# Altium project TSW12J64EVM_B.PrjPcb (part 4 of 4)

## Sheet TSW12J64EVM_B_10_InterfaceControl.SchDoc
size 431 x 279 mm; Date: Not shown in title block; ApprovedBy: Not shown in title block; CheckedBy: Not shown in title block; Author: Not shown in title block; CompanyName: Not shown in title block; Engineer: Not shown in title block; Organization: Not shown in title block; Address1: Not shown in title block; Address2: Not shown in title block; Address3: Not shown in title block; Address4: Not shown in title block; DocumentNumber: 10; Revision: Use project parameter SCH_Rev; SheetNumber: 10; SheetTotal: 11; PageSetup: Record=PageOptions¦CenterHorizontal=True¦CenterVertical=True¦PrintScale=1.00¦XCorrection=1.00¦YCorrection=1.00¦PrintKind=0¦BorderSize=5000000¦LeftOffset=0¦BottomOffset=0¦Orientation=2¦PaperLength=1000¦PaperWidth=1000¦Scale=100¦PaperSource=15¦PrintQuality=600¦MediaType=1¦DitherType=10¦PaperKind=Letter¦PrintScaleMode=1
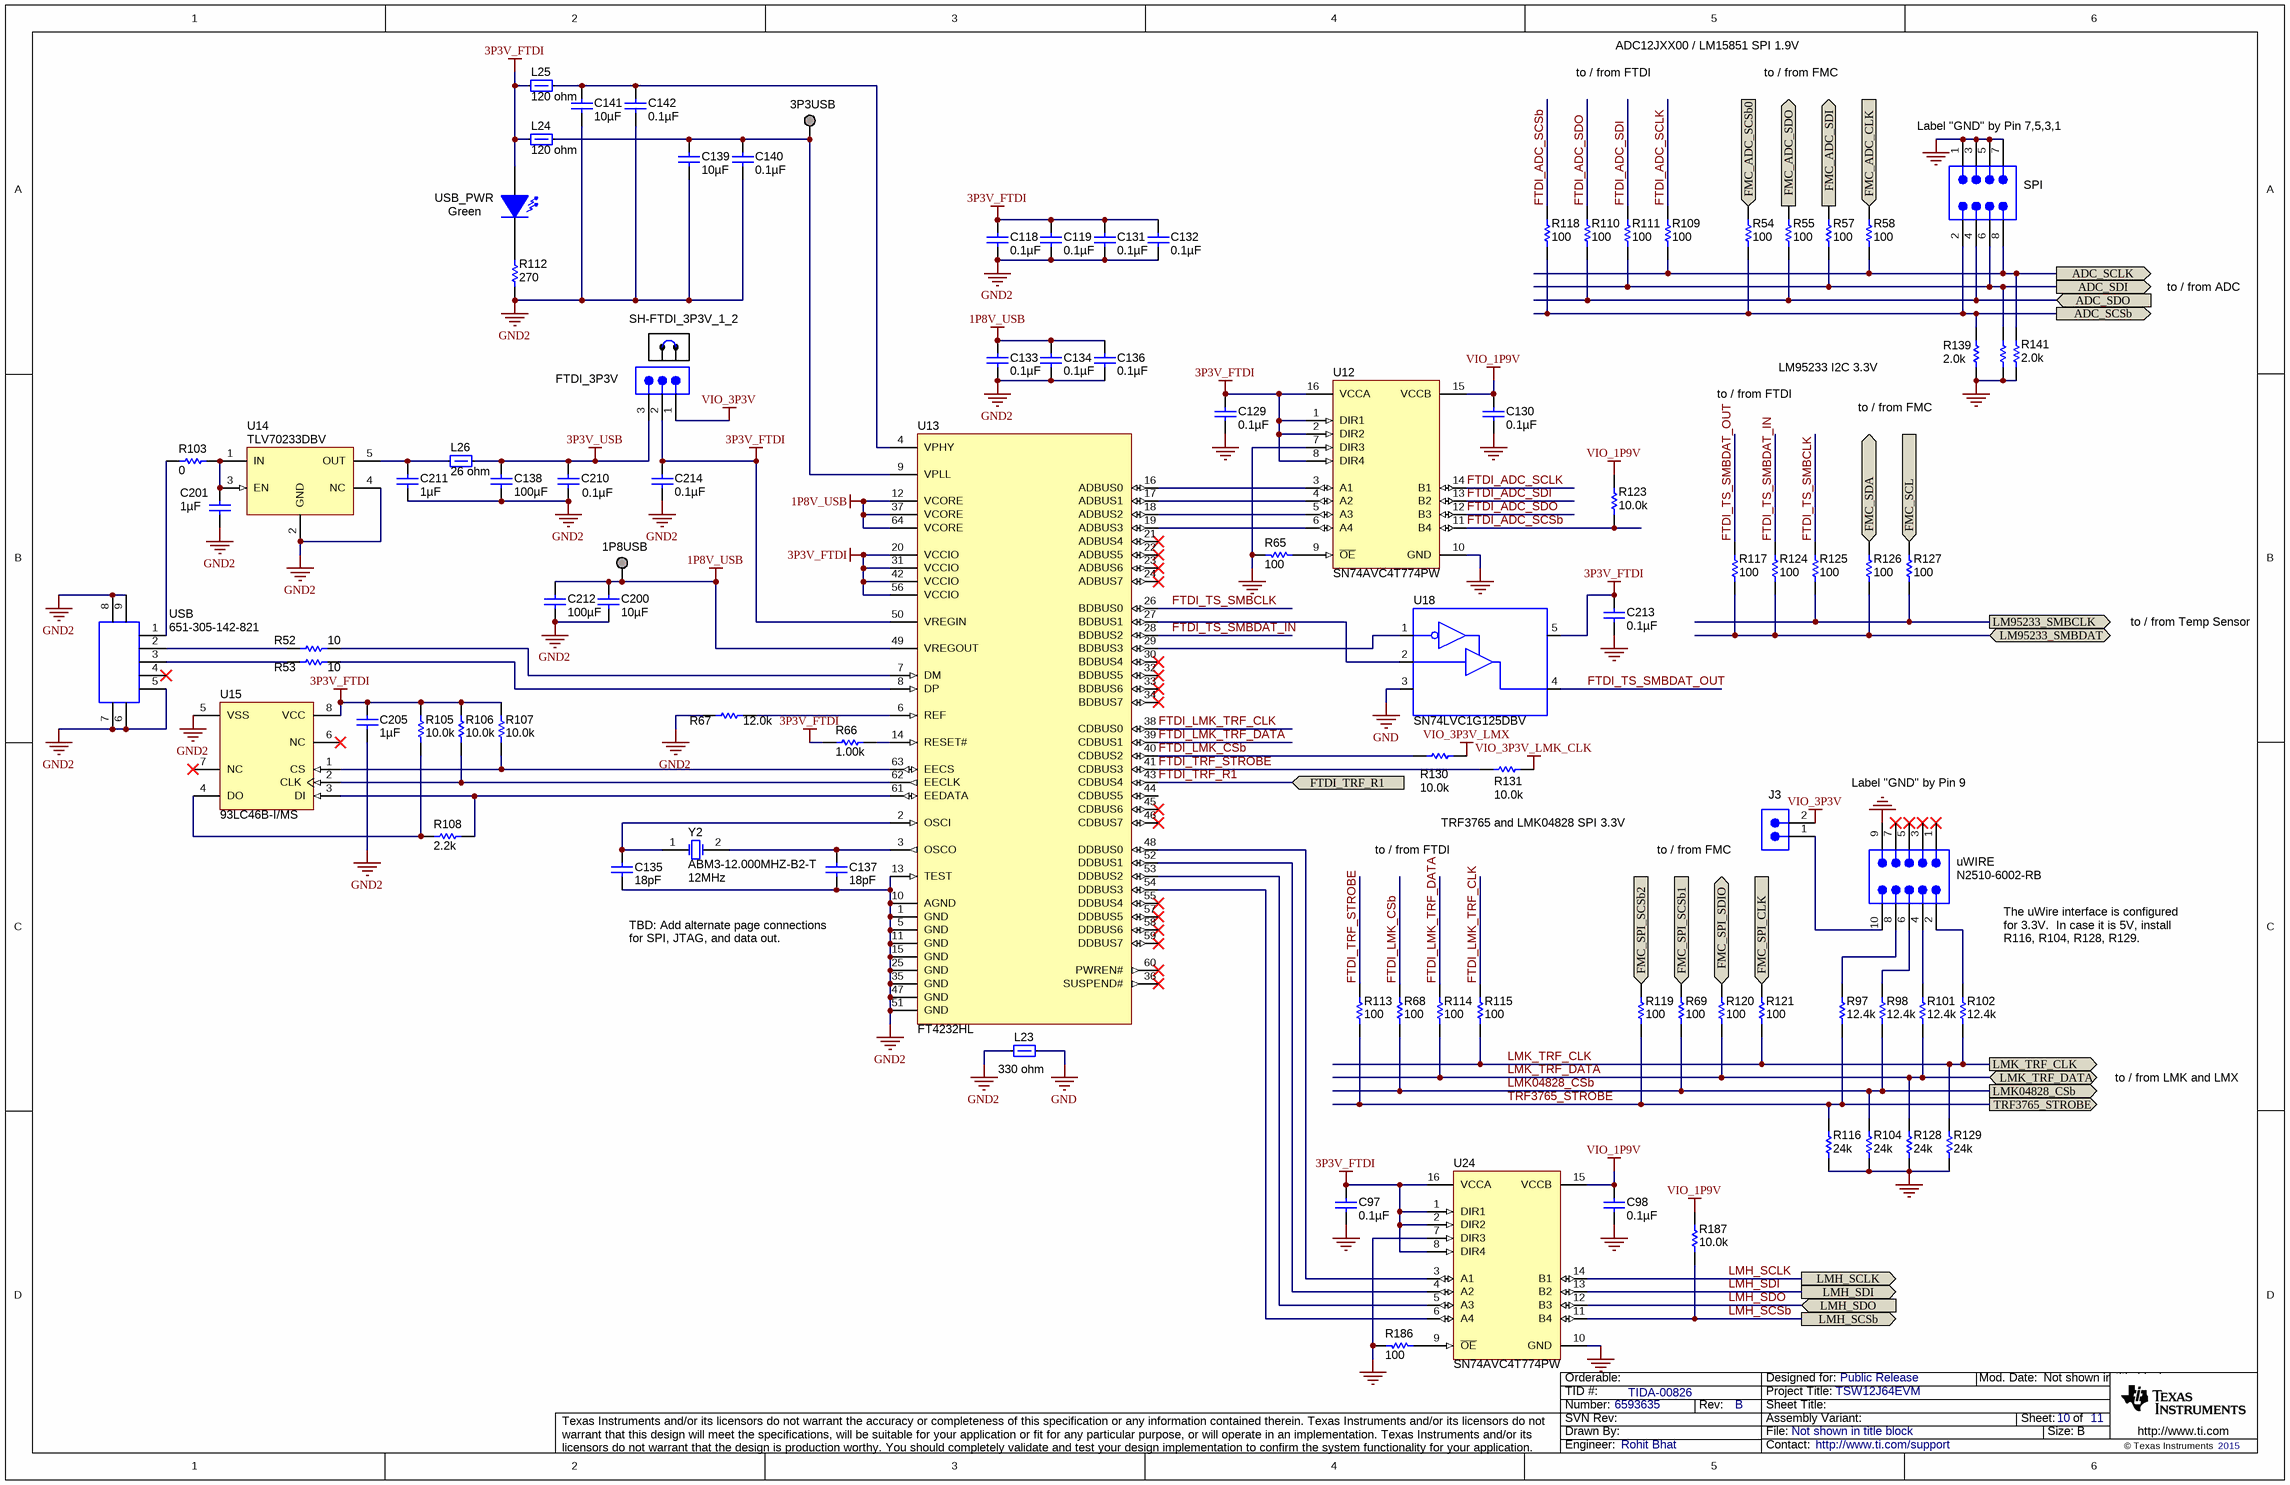
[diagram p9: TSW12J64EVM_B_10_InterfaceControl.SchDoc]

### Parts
1P8USB  TESTPOINT  [TESTPOINT]  (value not drawn)  (no BOM)
3P3USB  TESTPOINT  [TESTPOINT]  (value not drawn)  (no BOM)
C97  ValueDisplayed: 0.1µF  [0603L]  (hidden comment: 06033C104JAT2A)
C98  ValueDisplayed: 0.1µF  [0603L]  (hidden comment: 06033C104JAT2A)
C118  ValueDisplayed: 0.1µF  [0201]  (hidden comment: C0603X5R0J104K)
C119  ValueDisplayed: 0.1µF  [0201]  (hidden comment: C0603X5R0J104K)
C129  ValueDisplayed: 0.1µF  [0603L]  (hidden comment: 06033C104JAT2A)
C130  ValueDisplayed: 0.1µF  [0603L]  (hidden comment: 06033C104JAT2A)
C131  ValueDisplayed: 0.1µF  [0201]  (hidden comment: C0603X5R0J104K)
C132  ValueDisplayed: 0.1µF  [0201]  (hidden comment: C0603X5R0J104K)
C133  ValueDisplayed: 0.1µF  [0201]  (hidden comment: C0603X5R0J104K)
C134  ValueDisplayed: 0.1µF  [0201]  (hidden comment: C0603X5R0J104K)
C135  ValueDisplayed: 18pF  [0402L]  (hidden comment: GRM1555C1H180JA01D)
C136  ValueDisplayed: 0.1µF  [0201]  (hidden comment: C0603X5R0J104K)
C137  ValueDisplayed: 18pF  [0402L]  (hidden comment: GRM1555C1H180JA01D)
C138  ValueDisplayed: 100µF  [1206L]  (hidden comment: GRM31CR60J107ME39L)
C139  ValueDisplayed: 10µF  [0603L]  (hidden comment: C1608X5R1A106M)
C140  ValueDisplayed: 0.1µF  [0201]  (hidden comment: C0603X5R0J104K)
C141  ValueDisplayed: 10µF  [0603L]  (hidden comment: C1608X5R1A106M)
C142  ValueDisplayed: 0.1µF  [0201]  (hidden comment: C0603X5R0J104K)
C200  ValueDisplayed: 10µF  [0603L]  (hidden comment: C1608X5R1A106M)
C201  ValueDisplayed: 1µF  [0603L]  (hidden comment: C1608X5R1C105K)
C205  ValueDisplayed: 1µF  [0603L]  (hidden comment: C1608X5R1A105K)
C210  ValueDisplayed: 0.1µF  [0603L]  (hidden comment: 0603YC104JAT2A)
C211  ValueDisplayed: 1µF  [0603L]  (hidden comment: C1608X5R1C105K)
C212  ValueDisplayed: 100µF  [1206]  (hidden comment: GRM31CR60J107ME39L)
C213  ValueDisplayed: 0.1µF  [0603L]  (hidden comment: 06033C104JAT2A)
C214  ValueDisplayed: 0.1µF  [0201]  (hidden comment: C0603X5R0J104K)
FTDI_3P3V  TSW-103-07-G-S  [TSW-103-07-G-S]  (value not drawn)
J3  TSW-102-07-G-S  [TSW-102-07-G-S]  (value not drawn)
L23  value 330 ohm  [0603]  (hidden comment: BLM18SG331TN1D)
L24  value 120 ohm  [0603]  (hidden comment: BLM18SG121TN1D)
L25  value 120 ohm  [0603L]  (hidden comment: BLM18SG121TN1D)
L26  value 26 ohm  [0603]  (hidden comment: BLM18SG260TN1D)
R52  value 10  [0603L]  (hidden comment: CRCW060310R0JNEA)
R53  value 10  [0603L]  (hidden comment: CRCW060310R0JNEA)
R54  value 100  [0603L]  (hidden comment: CRCW0603100RJNEA)
R55  value 100  [0603L]  (hidden comment: CRCW0603100RJNEA)
R57  value 100  [0603L]  (hidden comment: CRCW0603100RJNEA)
R58  value 100  [0603L]  (hidden comment: CRCW0603100RJNEA)
R65  value 100  [0603L]  (hidden comment: CRCW0603100RJNEA)
R66  value 1.00k  [0603L]  (hidden comment: CRCW06031K00FKEA)
R67  value 12.0k  [0603L]  (hidden comment: RC0603FR-0712KL)
R68  value 100  [0603L]  (hidden comment: CRCW0603100RJNEA)
R69  value 100  [0603L]  (hidden comment: CRCW0603100RJNEA)
R97  value 12.4k  [0603L]  (hidden comment: CRCW060312K4FKEA)
R98  value 12.4k  [0603L]  (hidden comment: CRCW060312K4FKEA)
R101  value 12.4k  [0603L]  (hidden comment: CRCW060312K4FKEA)
R102  value 12.4k  [0603L]  (hidden comment: CRCW060312K4FKEA)
R103  value 0  [0603L]  (hidden comment: CRCW06030000Z0EA)
R104  value 24k  [0402L]  (hidden comment: CRCW040224K0JNED)
R105  value 10.0k  [0603L]  (hidden comment: CRCW060310K0FKEA)
R106  value 10.0k  [0603L]  (hidden comment: CRCW060310K0FKEA)
R107  value 10.0k  [0603L]  (hidden comment: CRCW060310K0FKEA)
R108  value 2.2k  [0603L]  (hidden comment: RC0603JR-072K2L)
R109  value 100  [0603L]  (hidden comment: CRCW0603100RJNEA)
R110  value 100  [0603L]  (hidden comment: CRCW0603100RJNEA)
R111  value 100  [0603L]  (hidden comment: CRCW0603100RJNEA)
R112  value 270  [0603L]  (hidden comment: CRCW0603270RJNEA)
R113  value 100  [0603L]  (hidden comment: CRCW0603100RJNEA)
R114  value 100  [0603L]  (hidden comment: CRCW0603100RJNEA)
R115  value 100  [0603L]  (hidden comment: CRCW0603100RJNEA)
R116  value 24k  [0402L]  (hidden comment: CRCW040224K0JNED)
R117  value 100  [0603L]  (hidden comment: CRCW0603100RJNEA)
R118  value 100  [0603L]  (hidden comment: CRCW0603100RJNEA)
R119  value 100  [0603L]  (hidden comment: CRCW0603100RJNEA)
R120  value 100  [0603L]  (hidden comment: CRCW0603100RJNEA)
R121  value 100  [0603L]  (hidden comment: CRCW0603100RJNEA)
R123  value 10.0k  [0603L]  (hidden comment: CRCW060310K0FKEA)
R124  value 100  [0603L]  (hidden comment: CRCW0603100RJNEA)
R125  value 100  [0603L]  (hidden comment: CRCW0603100RJNEA)
R126  value 100  [0603L]  (hidden comment: CRCW0603100RJNEA)
R127  value 100  [0603L]  (hidden comment: CRCW0603100RJNEA)
R128  value 24k  [0402L]  (hidden comment: CRCW040224K0JNED)
R129  value 24k  [0402L]  (hidden comment: CRCW040224K0JNED)
R130  value 10.0k  [0603L]  (hidden comment: CRCW060310K0FKEA)
R131  value 10.0k  [0603L]  (hidden comment: CRCW060310K0FKEA)
R139  value 2.0k  [0603L]  (hidden comment: CRCW06032K00JNEA)
R140  CRCW06032K00JNEA  [0603L]  (value not drawn)
R141  value 2.0k  [0603L]  (hidden comment: CRCW06032K00JNEA)
R186  value 100  [0603L]  (hidden comment: CRCW0603100RJNEA)
R187  value 10.0k  [0603L]  (hidden comment: CRCW060310K0FKEA)
SH-FTDI_3P3V_1_2  SNT-100-BK-G  [SNT-100-BK-G]  (value not drawn)
SPI  TSW-104-07-G-D  [TSW-104-07-G-D]  (value not drawn)
U12  SN74AVC4T774PW  [PW0016A_L]
U13  FT4232HL  [LQFP64_N]
U14  TLV70233DBV  [DBV0005A_N]
U15  93LC46B-I/MS  [MSOP-MS8_N]
U18  SN74LVC1G125DBV  [SOP-5_.95MM_(DBV)]
U24  SN74AVC4T774PW  [PW0016A_L]
USB  651-305-142-821  [CONN_USB-MINI-AB-651-305-142-821]
USB_PWR  value Green  [LED_LTST-C190]  (hidden comment: LTST-C190GKT)
uWIRE  N2510-6002-RB  [CONN_2510-6002]
Y2  ABM3-12.000MHZ-B2-T  Frequency: 12MHz  [XTAL_ABM3]

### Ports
ADC_SCLK (out), ADC_SCSb (out), ADC_SDI (out), ADC_SDO (in), FMC_ADC_CLK (in), FMC_ADC_SCSb0 (in), FMC_ADC_SDI (out), FMC_ADC_SDO (in), FMC_SCL (out), FMC_SDA (bidir), FMC_SPI_CLK (in), FMC_SPI_SCSb1 (in), FMC_SPI_SCSb2 (in), FMC_SPI_SDIO (bidir), FTDI_TRF_R1, LM95233_SMBCLK (out), LM95233_SMBDAT (bidir), LMH_SCLK (out), LMH_SCSb (out), LMH_SDI (out), LMH_SDO (in), LMK04828_CSb (out), LMK_TRF_CLK, LMK_TRF_DATA (bidir), TRF3765_STROBE (out)

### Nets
1P8V_USB: 1P8USB.1 C133.1 C134.1 C136.1 C200.1 C212.2 U13.12(VCORE) U13.37(VCORE) U13.49(VREGOUT) U13.64(VCORE)
3P3V_FTDI: C97.1 C118.1 C119.1 C129.1 C131.1 C132.1 C205.1 C213.1 C214.1 FTDI_3P3V.2 L24.1 L25.1 R66.2 R105.2 R106.2 R107.2 U12.1(DIR1) U12.2(DIR2) U12.8(DIR4) U12.16(VCCA) U13.20(VCCIO) U13.31(VCCIO) U13.42(VCCIO) U13.50(VREGIN) U13.56(VCCIO) U15.8(VCC) U18.5(VCC) U24.1(DIR1) U24.2(DIR2) U24.8(DIR4) U24.16(VCCA) USB_PWR.1(A)
3P3V_USB: C138.1 C210.1 FTDI_3P3V.3 L26.2
GND: C97.2 C98.2 C129.2 C130.2 C213.2 L23.2 R65.1 R104.1 R116.1 R128.1 R129.1 R139.1 R140.1 R141.1 R186.1 SPI.1 SPI.3 SPI.5 SPI.7 U12.7(DIR3) U12.10(GND) U18.3(GND) U24.7(DIR3) U24.10(GND) uWIRE.9
GND2: C118.2 C119.2 C131.2 C132.2 C133.2 C134.2 C135.2 C136.2 C137.2 C138.2 C139.2 C140.2 C141.2 C142.2 C200.2 C201.2 C205.2 C210.2 C211.2 C212.1 C214.2 L23.1 R67.1 R112.1 U13.1(GND) U13.5(GND) U13.10(AGND) U13.11(GND) U13.13(TEST) U13.15(GND) U13.25(GND) U13.35(GND) U13.47(GND) U13.51(GND) U14.2(GND) U14.4(NC) U15.5(VSS) USB.5 USB.6 USB.7 USB.8 USB.9
VIO_1P9V: C98.1 C130.1 R123.2 R187.2 U12.15(VCCB) U24.15(VCCB)
VIO_3P3V: FTDI_3P3V.1 J3.2
VIO_3P3V_LMK_CLK: R131.1
VIO_3P3V_LMX: R130.1
ADC_SCLK: R58.1 R109.1 R141.2 SPI.8 ; port ADC_SCLK
ADC_SCSb: R54.1 R118.1 R139.2 SPI.2 ; port ADC_SCSb
ADC_SDI: R57.1 R111.1 R140.2 SPI.6 ; port ADC_SDI
ADC_SDO: R55.1 R110.1 SPI.4 ; port ADC_SDO
FMC_ADC_CLK: R58.2 ; port FMC_ADC_CLK
FMC_ADC_SCSb0: R54.2 ; port FMC_ADC_SCSb0
FMC_ADC_SDI: R57.2 ; port FMC_ADC_SDI
FMC_ADC_SDO: R55.2 ; port FMC_ADC_SDO
FMC_SCL: R127.2 ; port FMC_SCL
FMC_SDA: R126.2 ; port FMC_SDA
FMC_SPI_CLK: R121.2 ; port FMC_SPI_CLK
FMC_SPI_SCSb1: R69.2 ; port FMC_SPI_SCSb1
FMC_SPI_SCSb2: R119.2 ; port FMC_SPI_SCSb2
FMC_SPI_SDIO: R120.2 ; port FMC_SPI_SDIO
FTDI_ADC_SCLK: R109.2 U12.14(B1)
FTDI_ADC_SCSb: R118.2 R123.1 U12.11(B4)
FTDI_ADC_SDI: R111.2 U12.13(B2)
FTDI_ADC_SDO: R110.2 U12.12(B3)
FTDI_LMK_CSb: R68.2 R130.2 U13.40(CDBUS2)
FTDI_LMK_TRF_CLK: R115.2 U13.38(CDBUS0)
FTDI_LMK_TRF_DATA: R114.2 U13.39(CDBUS1)
FTDI_TRF_R1: U13.43(CDBUS4) ; port FTDI_TRF_R1
FTDI_TRF_STROBE: R113.2 R131.2 U13.41(CDBUS3)
FTDI_TS_SMBCLK: R125.2 U13.26(BDBUS0)
FTDI_TS_SMBDAT_IN: R124.2 U13.28(BDBUS2)
FTDI_TS_SMBDAT_OUT: R117.2 U18.4(Y)
LM95233_SMBCLK: R125.1 R127.1 ; port LM95233_SMBCLK
LM95233_SMBDAT: R117.1 R124.1 R126.1 ; port LM95233_SMBDAT
LMH_SCLK: U24.14(B1) ; port LMH_SCLK
LMH_SCSb: R187.1 U24.11(B4) ; port LMH_SCSb
LMH_SDI: U24.13(B2) ; port LMH_SDI
LMH_SDO: U24.12(B3) ; port LMH_SDO
LMK04828_CSb: R68.1 R69.1 R98.1 R104.2 ; port LMK04828_CSb
LMK_TRF_CLK: R102.1 R115.1 R121.1 R129.2 ; port LMK_TRF_CLK
LMK_TRF_DATA: R101.1 R114.1 R120.1 R128.2 ; port LMK_TRF_DATA
TRF3765_STROBE: R97.1 R113.1 R116.2 R119.1 ; port TRF3765_STROBE
Net3P3USB_1: 3P3USB.1 C139.1 C140.1 L24.2 U13.9(VPLL)
NetC135_1: C135.1 U13.2(OSCI) Y2.1(OSC1)
NetC137_1: C137.1 U13.3(OSCO) Y2.2(OSC2)
NetC141_1: C141.1 C142.1 L25.2 U13.4(VPHY)
NetC201_1: C201.1 R103.2 U14.1(IN) U14.3(EN)
NetC211_1: C211.1 L26.1 U14.5(OUT)
NetJ3_1: J3.1 uWIRE.10
NetR52_1: R52.1 USB.2
NetR52_2: R52.2 U13.7(DM)
NetR53_1: R53.1 USB.3
NetR53_2: R53.2 U13.8(DP)
NetR65_2: R65.2 U12.9(~{OE})
NetR66_1: R66.1 U13.14(RESET#)
NetR67_2: R67.2 U13.6(REF)
NetR97_2: R97.2 uWIRE.8
NetR98_2: R98.2 uWIRE.6
NetR101_2: R101.2 uWIRE.4
NetR102_2: R102.2 uWIRE.2
NetR103_1: R103.1 USB.1
NetR105_1: R105.1 R108.2 U15.4(DO)
NetR106_1: R106.1 U13.62(EECLK) U15.2(CLK)
NetR107_1: R107.1 U13.63(EECS) U15.1(CS)
NetR108_1: R108.1 U13.61(EEDATA) U15.3(DI)
NetR112_2: R112.2 USB_PWR.2(K)
NetR186_2: R186.2 U24.9(~{OE})
NetU12_3: U12.3(A1) U13.16(ADBUS0)
NetU12_4: U12.4(A2) U13.17(ADBUS1)
NetU12_5: U12.5(A3) U13.18(ADBUS2)
NetU12_6: U12.6(A4) U13.19(ADBUS3)
NetU13_27: U13.27(BDBUS1) U18.2(A)
NetU13_29: U13.29(BDBUS3) U18.1(~OE)
NetU13_48: U13.48(DDBUS0) U24.3(A1)
NetU13_52: U13.52(DDBUS1) U24.4(A2)
NetU13_53: U13.53(DDBUS2) U24.5(A3)
NetU13_54: U13.54(DDBUS3) U24.6(A4)

Not connected (* = marked no-connect by the designer): U13 21(ADBUS4)* 22(ADBUS5)* 23(ADBUS6)* 24(ADBUS7)* 30(BDBUS4)* 32(BDBUS5)* 33(BDBUS6)* 34(BDBUS7)* 36(SUSPEND#)* 44(CDBUS5) 45(CDBUS6)* 46(CDBUS7)* 55(DDBUS4)* 57(DDBUS5)* 58(DDBUS6)* 59(DDBUS7)* 60(PWREN#)*; U15 6(NC)* 7(NC)*; USB 4*; uWIRE 1* 3* 5* 7*

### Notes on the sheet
- to / from FTDI
- ADC12JXX00 / LM15851 SPI 1.9V
- to / from FMC
- (near SPI) Label "GND" by Pin 7,5,3,1
- to / from ADC
- LM95233 I2C 3.3V
- to / from Temp Sensor
- TRF3765 and LMK04828 SPI 3.3V
- Label "GND" by Pin 9
- TBD: Add alternate page connections for SPI, JTAG, and data out.
- The uWire interface is configured for 3.3V.  In case it is 5V, install R116, R104, R128, R129.
- to / from LMK and LMX

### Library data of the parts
1P8USB 3P3USB = TESTPOINT: TEST POINT.  No entry in BOM.
C97 C98 C129 C130 C213 = 06033C104JAT2A: CAP, CERM, 0.1uF, 25V, +/-5%, X7R, 0603; Manufacturer: AVX; Polarized: N; CompType: Capacitor; U/M: EA; Cap_F: 0.0000001; Tolerance_%: 5; ESR_Ohm: 0.05; Value1: 0.05 ohm; VDC_V: 25; TaMin_C: -55; TaMax_C: 125; Cap_Case: 0603
C118 C119 C131-C134 C136 C140 C142 C214 = Capacitor: CAP, CERM, 0.1uF, 6.3V, X5R, 10%, 0201; Manufacturer: TDK; Polarized: N; U/M: EA
C135 C137 = GRM1555C1H180JA01D: CAP, CERM, 18pF, 50V, +/-5%, C0G/NP0, 0402; Manufacturer: MuRata; Polarized: N; CompType: Capacitor; U/M: EA; Cap_F: 0.000000000018; Tolerance_%: 5; Value1: Unknown; VDC_V: 50; TaMin_C: -55; TaMax_C: 125; Cap_Case: 0402
C138 = GRM31CR60J107ME39L: CAP, CERM, 100uF, 6.3V, +/-20%, X5R, 1206; Manufacturer: MuRata; Polarized: N; CompType: Capacitor; U/M: EA; Cap_F: 0.0001; Tolerance_%: 20; ESR_Ohm: 0.003; Value1: 0.003 ohm; VDC_V: 6.3; TaMin_C: -55; TaMax_C: 85; Cap_Case: 1206
C139 C141 C200 = C1608X5R1A106M: CAP, CERM, 10uF, 10V, +/-10%, C0G/NP0, 0603; Manufacturer: TDK; Polarized: N; CompType: Capacitor; U/M: EA; Cap_F: 0.00001; Tolerance_%: 10; ESR_Ohm: 0.0078; Value1: 0.0078 ohm; IRMS_A: 1.85; TaMin_C: -55; TaMax_C: 85; Cap_Case: 0603
C201 C211 = C1608X5R1C105K: CAP, CERM, 1uF, 16V, +/-10%, X5R, 0603; Manufacturer: TDK; Polarized: N; CompType: Capacitor; U/M: EA; Cap_F: 0.000001; Tolerance_%: 10; ESR_Ohm: 0.0057; Value1: 0.0057 ohm; VDC_V: 16; TaMin_C: -55; TaMax_C: 85; Cap_Case: 0603
C205 = C1608X5R1A105K: CAP, CERM, 1uF, 10V, +/-10%, X5R, 0603; Manufacturer: TDK; Polarized: N; CompType: Capacitor; U/M: EA; Cap_F: 0.000001; Tolerance_%: 10; ESR_Ohm: 0.0057; Value1: 0.0057 ohm; TaMin_C: -55; TaMax_C: 85; Cap_Case: 0603
C210 = 0603YC104JAT2A: CAP, CERM, 0.1uF, 16V, +/-5%, X7R, 0603; Manufacturer: AVX; Polarized: N; CompType: Capacitor; U/M: EA; Cap_F: 0.0000001; Tolerance_%: 5; ESR_Ohm: 0.039; Value1: 0.039 ohm; VDC_V: 16; TaMin_C: -55; TaMax_C: 125; Cap_Case: 0603
C212 = GRM31CR60J107ME39L: CAP, CERM, 100uF, 6.3V, +/-20%, X5R, 1206; Manufacturer: MuRata; Polarized: N; CompType: Capacitor; U/M: EA; Cap_F: 0.0001; Tolerance_%: 20; ESR_Ohm: 0.003; Value1: 0.003 ohm; VDC_V: 6.3; TaMin_C: -55; TaMax_C: 85
FTDI_3P3V = TSW-103-07-G-S: Header, TH, 100mil, 3x1, Gold plated, 230 mil above insulator; Manufacturer: Samtec, Inc.; Alternate Manufacturer: Any; Alternate PartNumber: Equivalent; U/M: EA
J3 = TSW-102-07-G-S: Header, TH, 100mil, 2x1, Gold plated, 230 mil above insulator; Manufacturer: Samtec, Inc.; U/M: EA
L23 = BLM18SG331TN1D: 1.5A Ferrite Bead, 330 ohm @ 100MHz, SMD; Manufacturer: MuRata; Imax_A: 1.5; DCR_ohm: 0.07; Value1: 0.07 ohm; ZTyp@100MHz_Ohm: 330; U/M: EA
L24 L25 = BLM18SG121TN1D: 3A Ferrite Bead, 120 ohm @ 100MHz, SMD; Manufacturer: MuRata; Imax_A: 3; DCR_ohm: 0.025; Value1: 0.025 ohm; ZTyp@100MHz_Ohm: 120; U/M: EA
L26 = BLM18SG260TN1D: 6A Ferrite Bead, 26 ohm @ 100MHz, SMD; Manufacturer: MuRata; Imax_A: 6; DCR_ohm: 0.007; Value1: 0.007 ohm; ZTyp@100MHz_Ohm: 26; U/M: EA
R52 R53 = CRCW060310R0JNEA: RES, 10 ohm, 5%, 0.1W, 0603; Manufacturer: Vishay-Dale; CompType: Resistor; Value_Code: 10R0; Tolerance_%: 5; Power_W: 0.1; VDC_V: 75; TempCo: 200 ppm/C; EIA_Code: E24; U/M: EA
R54 R55 R57 R58 R65 R68 R69 R109-R111 R113-R115 R117-R121 R124-R127 R186 = CRCW0603100RJNEA: RES, 100 ohm, 5%, 0.1W, 0603; Manufacturer: Vishay-Dale; CompType: Resistor; Value_Code: 100R; Tolerance_%: 5; Power_W: 0.1; VDC_V: 75; TempCo: 200 ppm/C; EIA_Code: E24; U/M: EA
R66 = CRCW06031K00FKEA: RES, 1.00k ohm, 1%, 0.1W, 0603; Manufacturer: Vishay-Dale; CompType: Resistor; Tolerance_%: 1; VDC_V: 75; Power_W: 0.1; Res_ohm: 1000; TempCo_ppm/C: 100; Value_Code: 1k00; EIA_Code: E96; U/M: EA
R67 = RC0603FR-0712KL: RES, 12.0k ohm, 1%, 0.1W, 0603; Manufacturer: Yageo America; CompType: Resistor; Res_ohm: 12000; Value_Code: 12k0; Tolerance_%: 1; Power_W: 0.1; VDC_V: 150; TempCo: 200 ppm/C; U/M: EA
R97 R98 R101 R102 = CRCW060312K4FKEA: RES, 12.4k ohm, 1%, 0.1W, 0603; Manufacturer: Vishay-Dale; CompType: Resistor; Res_ohm: 12400; Value_Code: 12k4; Tolerance_%: 1; Power_W: 0.1; VDC_V: 75; TempCo: 100 ppm/C; EIA_Code: E96; U/M: EA
R103 = CRCW06030000Z0EA: RES, 0 ohm, 5%, 0.1W, 0603; Manufacturer: Vishay-Dale; CompType: Resistor; Value_Code: 0000; Tolerance_%: 5; Power_W: 0.1; VDC_V: 75; TempCo: 200 ppm/C; EIA_Code: E24; U/M: EA
R104 R116 R128 R129 = CRCW040224K0JNED: RES, 24k ohm, 5%, 0.063W, 0402; Manufacturer: Vishay-Dale; CompType: Resistor; Res_ohm: 24000; Value_Code: 24k0; Tolerance_%: 5; Power_W: 0.063; VDC_V: 50; TempCo: 200 ppm/C; EIA_Code: E24; U/M: EA
R105-R107 R123 R130 R131 R187 = CRCW060310K0FKEA: RES, 10.0k ohm, 1%, 0.1W, 0603; Manufacturer: Vishay-Dale; CompType: Resistor; Res_ohm: 10000; Value_Code: 10k0; Tolerance_%: 1; Power_W: 0.1; VDC_V: 75; TempCo: 100 ppm/C; EIA_Code: E96; U/M: EA
R108 = RC0603JR-072K2L: RES, 2.2k ohm, 5%, 0.1W, 0603; Manufacturer: Yageo America; CompType: Resistor; Res_ohm: 2200; Value_Code: 2k20; Tolerance_%: 5; Power_W: 0.1; VDC_V: 50; TempCo: 100 ppm/C; EIA_Code: E24; U/M: EA
R112 = CRCW0603270RJNEA: RES, 270 ohm, 5%, 0.1W, 0603; Manufacturer: Vishay-Dale; Alternate Manufacturer: Any; Alternate PartNumber: Equivalent; CompType: Resistor; Value_Code: 270R; Tolerance_%: 5; Power_W: 0.1; VDC_V: 75; TempCo: 200 ppm/C; EIA_Code: E24; U/M: EA
R139-R141 = CRCW06032K00JNEA: RES, 2.0k ohm, 5%, 0.1W, 0603; Manufacturer: Vishay-Dale; CompType: Resistor; Res_ohm: 2000; Value_Code: 2k00; Tolerance_%: 5; Power_W: 0.1; VDC_V: 75; TempCo: 200 ppm/C; EIA_Code: E24; U/M: EA
SH-FTDI_3P3V_1_2 = SNT-100-BK-G: Shunt, 100mil, Gold plated, Black; Manufacturer: Samtec, Inc.; Alternate Manufacturer: 3M; Alternate PartNumber: 969102-0000-DA; Value: 1x2; Note: You can "mate" this to a header by matching the designator.  i.e. use SH-J3 for header J3
SPI = TSW-104-07-G-D: Header, TH, 100mil, 4x2, Gold plated, 230 mil above insulator; Manufacturer: Samtec, Inc.; U/M: EA
U12 U24 = SN74AVC4T774PW: 4-BIT DUAL-SUPPLY BUS TRANSCEIVER WITH CONFIGURABLE VOLTAGE TRANSLATION AND 3-STATE OUTPUTS, PW0016A; Alternate Manufacturer: None; Manufacturer: Texas Instruments; SymbolCreator: a0411947; CompType: IC; U/M: EA
U13 = FT4232HL: Quad High Speed USB to Multipurpose UART/MPSSE IC; Manufacturer: FTDI; SymbolCreator: a0411947
U14 = TLV70233DBV: 300-mA, Low-IQ, Low-Dropout Regulator, DBV0005A; Alternate Manufacturer: None; Manufacturer: Texas Instruments; SymbolCreator: a0411947; CompType: IC; U/M: EA
U15 = 93LC46B-I/MS: 1K, 64x16-bit, 2.5V Microwire Serial EEPROM, 8-Pin MSOP, Industrial Temperature; Manufacturer: Microchip Technology
U18 = SN74LVC1G125DBV: IC, Single Bus Buffer Gate With 3-States Output; Manufacturer: TI; Alternate Manufacturer: None; Area: 24,883
USB = 651-305-142-821: MINI USB 2.0 SMT TYPE AB 5 CONTACTS R/A, SMD; Manufacturer: Wurth Elektronik eiSos; SymbolCreator: a0799628; CompType: Connector; U/M: EA
USB_PWR = LTST-C190GKT: LED, Green, SMD; Manufacturer: Lite-On; Vf_V: 2.1; Value2: 2.1V; Io_A: 0.02; Power_TotalModule: 0.1; Value1: 0.1W; U/M: EA
uWIRE = N2510-6002-RB: Connector, 100mil Shrouded, 5x2, High-Temperature, Gold, TH; Manufacturer: 3M; SymbolCreator: a0412235; U/M: EA
Y2 = ABM3-12.000MHZ-B2-T: Crystal, 12Mhz, 18pF, SMD; Manufacturer: Abracon Corportation; SymbolCreator: a0412235; U/M: EA; TaMin_C: -20; TaMax_C: 70; Frequency Stability: ±50ppm

## Sheet TSW12J64EVM_B_11_Hardware.SchDoc
size 431 x 279 mm; Date: Not shown in title block; ApprovedBy: Not shown in title block; CheckedBy: Not shown in title block; Author: Not shown in title block; CompanyName: Not shown in title block; Engineer: Not shown in title block; Organization: Not shown in title block; Address1: Not shown in title block; Address2: Not shown in title block; Address3: Not shown in title block; Address4: Not shown in title block; DocumentNumber: 11; Revision: Use project parameter SCH_Rev; SheetNumber: 11; SheetTotal: 11; PageSetup: Record=PageOptions¦CenterHorizontal=True¦CenterVertical=True¦PrintScale=1.00¦XCorrection=1.00¦YCorrection=1.00¦PrintKind=0¦BorderSize=5000000¦LeftOffset=0¦BottomOffset=0¦Orientation=2¦PaperLength=1000¦PaperWidth=1000¦Scale=100¦PaperSource=15¦PrintQuality=600¦MediaType=1¦DitherType=10¦PaperKind=Letter¦PrintScaleMode=1
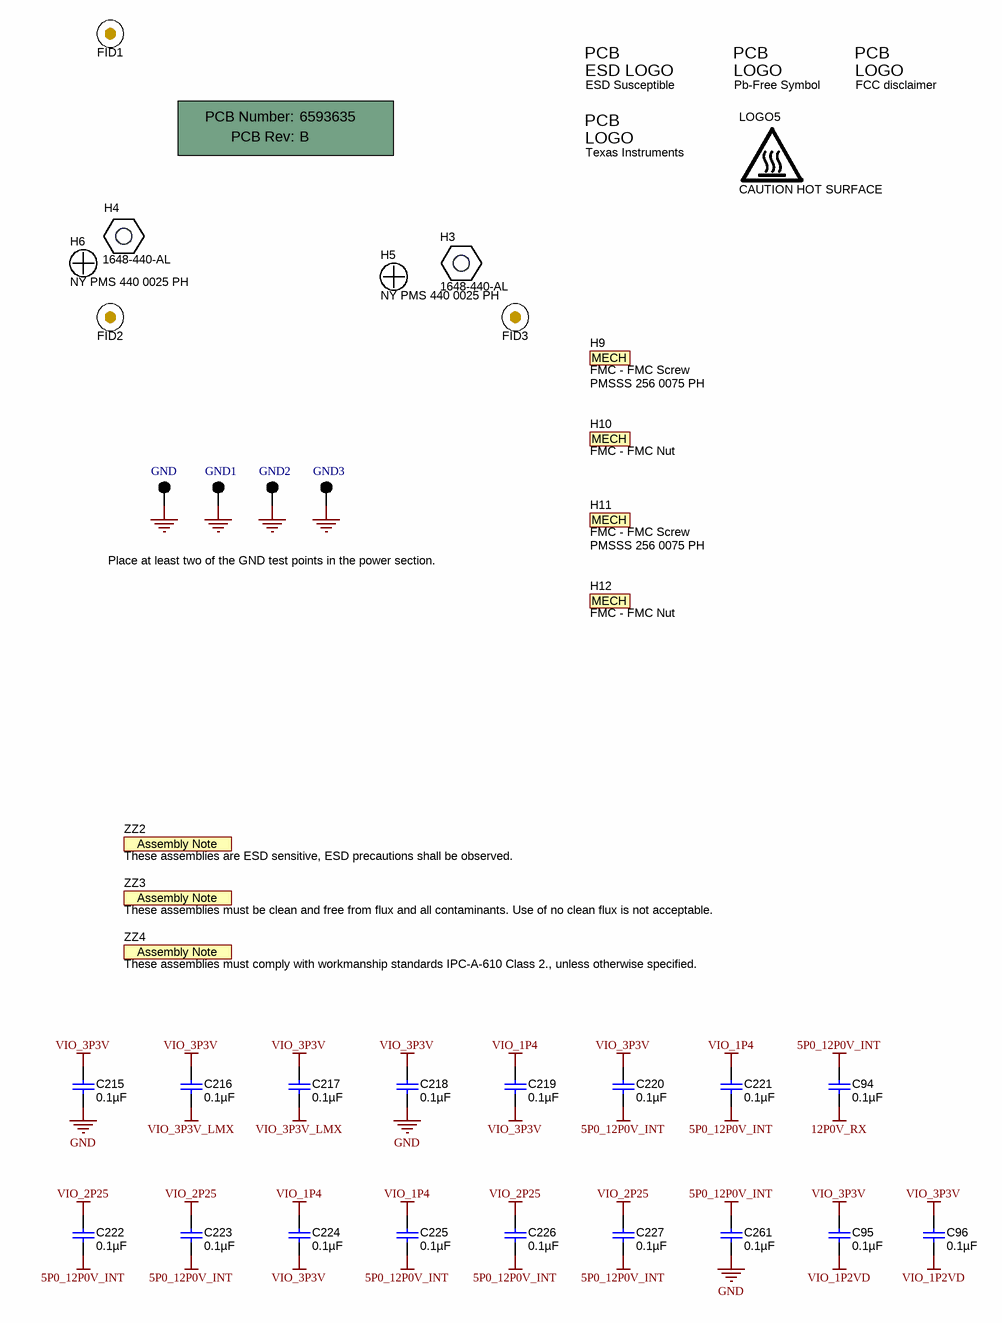
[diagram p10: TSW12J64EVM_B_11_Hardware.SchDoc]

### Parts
!PCB  Printed Circuit Board  (value not drawn)  (mechanical)
C94  ValueDisplayed: 0.1µF  [0402L]  (hidden comment: GRM155R71A104KA01D)
C95  ValueDisplayed: 0.1µF  [0402L]  (hidden comment: GRM155R71A104KA01D)
C96  ValueDisplayed: 0.1µF  [0402L]  (hidden comment: GRM155R71A104KA01D)
C215  ValueDisplayed: 0.1µF  [0402L]  (hidden comment: GRM155R71A104KA01D)
C216  ValueDisplayed: 0.1µF  [0402L]  (hidden comment: GRM155R71A104KA01D)
C217  ValueDisplayed: 0.1µF  [0402L]  (hidden comment: GRM155R71A104KA01D)
C218  ValueDisplayed: 0.1µF  [0402L]  (hidden comment: GRM155R71A104KA01D)
C219  ValueDisplayed: 0.1µF  [0402L]  (hidden comment: GRM155R71A104KA01D)
C220  ValueDisplayed: 0.1µF  [0402L]  (hidden comment: GRM155R71A104KA01D)
C221  ValueDisplayed: 0.1µF  [0402L]  (hidden comment: GRM155R71A104KA01D)
C222  ValueDisplayed: 0.1µF  [0402L]  (hidden comment: GRM155R71A104KA01D)
C223  ValueDisplayed: 0.1µF  [0402L]  (hidden comment: GRM155R71A104KA01D)
C224  ValueDisplayed: 0.1µF  [0402L]  (hidden comment: GRM155R71A104KA01D)
C225  ValueDisplayed: 0.1µF  [0402L]  (hidden comment: GRM155R71A104KA01D)
C226  ValueDisplayed: 0.1µF  [0402L]  (hidden comment: GRM155R71A104KA01D)
C227  ValueDisplayed: 0.1µF  [0402L]  (hidden comment: GRM155R71A104KA01D)
C261  ValueDisplayed: 0.1µF  [0402L]  (hidden comment: GRM155R71A104KA01D)
FID1  Fiducial  [Fiducial10-30]  (value not drawn)
FID2  Fiducial  [Fiducial10-30]  (value not drawn)
FID3  Fiducial  [Fiducial10-30]  (value not drawn)
GND  5011  [Keystone5011]  (value not drawn)
GND1  5011  [Keystone5011]  (value not drawn)
GND2  5011  [Keystone5011]  (value not drawn)
GND3  5011  [Keystone5011]  (value not drawn)
H3  1648-440-AL  [Keystone_1902C]
H4  1648-440-AL  [Keystone_1902C]
H5  NY PMS 440 0025 PH  [NY PMS 440 0025 PH]
H6  NY PMS 440 0025 PH  [NY PMS 440 0025 PH]
H9  FMC - FMC Screw  PartNumber: PMSSS 256 0075 PH  (mechanical)
H10  FMC - FMC Nut  (mechanical)
H11  FMC - FMC Screw  PartNumber: PMSSS 256 0075 PH  (mechanical)
H12  FMC - FMC Nut  (mechanical)
Logo1  ESD Susceptible  [ESD_Overlay_Small]  (no BOM)
Logo2  Texas Instruments  [TI_Symbol_Overlay_Small]  (no BOM)
Logo3  Pb-Free Symbol  [Pb-Free_Overlay_Small]  (no BOM)
Logo4  FCC disclaimer  [FCC_disclaimer]  (no BOM)
LOGO5  CAUTION HOT SURFACE  [IEC_HotSurface_Small]  (no BOM)
ZZ2  These assemblies are ESD sensitive, ESD precautions shall be observed.  [AssemblyNote]  (no BOM)
ZZ3  These assemblies must be clean and free from flux and all contaminants. Use of no clean flux is not acceptable.  [AssemblyNote]  (no BOM)
ZZ4  These assemblies must comply with workmanship standards IPC-A-610 Class 2., unless otherwise specified.  [AssemblyNote]  (no BOM)

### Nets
5P0_12P0V_INT: C94.1 C220.2 C221.2 C222.2 C223.2 C225.2 C226.2 C227.2 C261.1
12P0V_RX: C94.2
GND: C215.2 C218.2 C261.2 GND.1 GND1.1 GND2.1 GND3.1
VIO_1P2VD: C95.2 C96.2
VIO_1P4: C219.1 C221.1 C224.1 C225.1
VIO_2P25: C222.1 C223.1 C226.1 C227.1
VIO_3P3V: C95.1 C96.1 C215.1 C216.1 C217.1 C218.1 C219.2 C220.1 C224.2
VIO_3P3V_LMX: C216.2 C217.2

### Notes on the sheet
- Place at least two of the GND test points in the power section.

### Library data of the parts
!PCB = PCB: Manufacturer: Any; PartNumber: 6593635; SymbolCreator: a0412235
C94-C96 C215-C227 C261 = GRM155R71A104KA01D: CAP, CERM, 0.1uF, 10V, +/-10%, X7R, 0402; Manufacturer: MuRata; Polarized: N; CompType: Capacitor; U/M: EA; Cap_F: 0.0000001; Tolerance_%: 10; TaMin_C: -55; TaMax_C: 125; Cap_Case: 0402
FID1-FID3 = Fiducial: Fiducial mark.  There is nothing to buy or mount.; SymbolCreator: codlsc
GND GND1-GND3 = 5011: Test Point, TH, Multipurpose, Black; Manufacturer: Keystone Electronics; CompType: Test Point Loop
H3 H4 = 1902C: Standoff, Round, 3/16"  x 1-3/16"L #4-40 Aluminum; Manufacturer: RAF; CompType: Hardware; U/M: EA
H5 H6 = NY PMS 440 0025 PH: Machine Screw, Round, #4-40 x 1/4, Nylon, Philips panhead; Manufacturer: B&F Fastener Supply; CompType: Hardware; SymbolCreator: codlsc; U/M: EA
H9 H11 = MechPart: MACHINE SCREW PAN PHILLIPS 2-56; Manufacturer: B&F Fastner Supply; SymbolCreator: codlsc; CompType: Mechanical; U/M: EA
H10 H12 = MechPart: HEX NUT 3/16" STN STEEL 2-56; Manufacturer: B & F Fastener Supply; PartNumber: HNSS256; SymbolCreator: codlsc; CompType: Mechanical; U/M: EA
Logo1 = ESD_Susceptible: ESD Susceptible Symbol; SymbolCreator: codlsc
Logo2 = TI_Logo: Texas Instrument Corporate Signature; SymbolCreator: codlsc
Logo3 = Pb-Free: SymbolCreator: a0412235
Logo4 = FCC_disclaimer: SymbolCreator: codlsc
LOGO5 = IEC_HotSurface: IEC 61010-1 Hot Surface Warning; SymbolCreator: a0412235
ZZ2-ZZ4 = AssemblyNote: SymbolCreator: codlsc

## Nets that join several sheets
5P0_12P0V_INT: TSW12J64EVM_B_8_Power (16 pins), TSW12J64EVM_B_9_Power (C382.1 C383.1 U43.2), TSW12J64EVM_B_11_Hardware (9 pins)
12P0V_RX: TSW12J64EVM_B_5_FMC (FMC_RX1.C35 FMC_RX1.C37), TSW12J64EVM_B_8_Power (EXT5V_FMC12V.3), TSW12J64EVM_B_11_Hardware (C94.2)
GND: TSW12J64EVM_B_1_FRONT_END (26 pins), TSW12J64EVM_B_2_RELAY_CONTROL (75 pins), TSW12J64EVM_B_3_ANALOG_IN (30 pins), TSW12J64EVM_B_4_ADC_IO (87 pins), TSW12J64EVM_B_5_FMC (164 pins), TSW12J64EVM_B_6_TRF3765 (64 pins), TSW12J64EVM_B_8_Power (82 pins), TSW12J64EVM_B_9_Power (76 pins), TSW12J64EVM_B_10_InterfaceControl (25 pins), TSW12J64EVM_B_11_Hardware (7 pins)
VIO_1P2VA: TSW12J64EVM_B_4_ADC_IO (18 pins), TSW12J64EVM_B_8_Power (C177.1 C188.1 L15.2)
VIO_1P2VD: TSW12J64EVM_B_4_ADC_IO (28 pins), TSW12J64EVM_B_8_Power (C189.1 C197.1 L16.2), TSW12J64EVM_B_11_Hardware (C95.2 C96.2)
VIO_1P4: TSW12J64EVM_B_8_Power (5 pins), TSW12J64EVM_B_11_Hardware (C219.1 C221.1 C224.1 C225.1)
VIO_1P9V: TSW12J64EVM_B_4_ADC_IO (20 pins), TSW12J64EVM_B_8_Power (6 pins), TSW12J64EVM_B_9_Power (5 pins), TSW12J64EVM_B_10_InterfaceControl (6 pins)
VIO_2P25: TSW12J64EVM_B_8_Power (5 pins), TSW12J64EVM_B_11_Hardware (C222.1 C223.1 C226.1 C227.1)
VIO_3: TSW12J64EVM_B_1_FRONT_END (D3.2), TSW12J64EVM_B_9_Power (C410.1 C411.1 L54.2)
VIO_3P3V: TSW12J64EVM_B_4_ADC_IO (15 pins), TSW12J64EVM_B_8_Power (C153.1 C163.1 L9.2), TSW12J64EVM_B_10_InterfaceControl (FTDI_3P3V.1 J3.2), TSW12J64EVM_B_11_Hardware (9 pins)
VIO_3P3V_LMK_CLK: TSW12J64EVM_B_8_Power (C116.1 C171.1 L13.2), TSW12J64EVM_B_10_InterfaceControl (R131.1)
VIO_3P3V_LMX: TSW12J64EVM_B_6_TRF3765 (19 pins), TSW12J64EVM_B_8_Power (C144.1 C152.1 L6.2), TSW12J64EVM_B_10_InterfaceControl (R130.1), TSW12J64EVM_B_11_Hardware (C216.2 C217.2)
VIO_3P75_U19: TSW12J64EVM_B_3_ANALOG_IN (13 pins), TSW12J64EVM_B_9_Power (C280.1 C281.1 L43.2 VIO_3P75_U19.1)
VIO_3P75_U23: TSW12J64EVM_B_3_ANALOG_IN (12 pins), TSW12J64EVM_B_4_ADC_IO (R183.1), TSW12J64EVM_B_9_Power (C297.1 C298.1 L45.2 VIO_3P75_U23.1)
VIO_4P05V: TSW12J64EVM_B_8_Power (6 pins), TSW12J64EVM_B_9_Power (L35.1 L36.1 L40.1 L53.1)
VIO_5V_DRV: TSW12J64EVM_B_2_RELAY_CONTROL (14 pins), TSW12J64EVM_B_9_Power (C401.1 C402.1 FL2.3 VIO_5V_DRV.1)
VIO_5V_LMC: TSW12J64EVM_B_2_RELAY_CONTROL (62 pins), TSW12J64EVM_B_9_Power (C395.1 C396.1 FL1.3 VIO_5V_LMC.1)
VIO_5V_LMH: TSW12J64EVM_B_1_FRONT_END (C353.1 C413.1 OFFSET_ADJ.1 U40.5), TSW12J64EVM_B_9_Power (C391.1 C392.1 L51.2 VIO_5V_LMH.1)
VIO_5V_LOGIC: TSW12J64EVM_B_1_FRONT_END (10 pins), TSW12J64EVM_B_9_Power (C398.1 C399.1 FL3.3 VIO_5V_LOGIC.1)
VIO_-1P25_U19: TSW12J64EVM_B_3_ANALOG_IN (10 pins), TSW12J64EVM_B_9_Power (C289.1 C290.1 L44.2 VIO_-1P25_U19.1)
VIO_-1P25_U23: TSW12J64EVM_B_3_ANALOG_IN (9 pins), TSW12J64EVM_B_4_ADC_IO (R182.1), TSW12J64EVM_B_9_Power (C299.1 C300.1 L46.2 VIO_-1P25_U23.1)
VIO_-3: TSW12J64EVM_B_1_FRONT_END (D3.1), TSW12J64EVM_B_9_Power (C404.1 C405.1 L52.2)
VIO_-3_LMH: TSW12J64EVM_B_1_FRONT_END (C354.1 C414.2 OFFSET_ADJ.3 U40.2), TSW12J64EVM_B_9_Power (C358.1 C359.1 L48.2)
ADC_OR_T0: TSW12J64EVM_B_4_ADC_IO (D2.2 OR.3 U2.25), TSW12J64EVM_B_5_FMC (FMC_RX1.G27)
ADC_OR_T1: TSW12J64EVM_B_4_ADC_IO (D4.2 OR.1 U2.26), TSW12J64EVM_B_5_FMC (FMC_RX1.D26)
ADC_SCLK: TSW12J64EVM_B_4_ADC_IO (U2.58), TSW12J64EVM_B_10_InterfaceControl (R58.1 R109.1 R141.2 SPI.8)
ADC_SCSb: TSW12J64EVM_B_4_ADC_IO (U2.59), TSW12J64EVM_B_10_InterfaceControl (R54.1 R118.1 R139.2 SPI.2)
ADC_SDI: TSW12J64EVM_B_4_ADC_IO (U2.57), TSW12J64EVM_B_10_InterfaceControl (R57.1 R111.1 R140.2 SPI.6)
ADC_SDO: TSW12J64EVM_B_4_ADC_IO (U2.56), TSW12J64EVM_B_10_InterfaceControl (R55.1 R110.1 SPI.4)
D0_N: TSW12J64EVM_B_4_ADC_IO (C9.1), TSW12J64EVM_B_5_FMC (FMC_RX1.C6)
D0_P: TSW12J64EVM_B_4_ADC_IO (C7.1), TSW12J64EVM_B_5_FMC (FMC_RX1.C7)
D1_N: TSW12J64EVM_B_4_ADC_IO (C12.1), TSW12J64EVM_B_5_FMC (FMC_RX1.A2)
D1_P: TSW12J64EVM_B_4_ADC_IO (C10.1), TSW12J64EVM_B_5_FMC (FMC_RX1.A3)
D2_N: TSW12J64EVM_B_4_ADC_IO (C14.1), TSW12J64EVM_B_5_FMC (FMC_RX1.A6)
D2_P: TSW12J64EVM_B_4_ADC_IO (C13.1), TSW12J64EVM_B_5_FMC (FMC_RX1.A7)
D3_N: TSW12J64EVM_B_4_ADC_IO (C17.1), TSW12J64EVM_B_5_FMC (FMC_RX1.A10)
D3_P: TSW12J64EVM_B_4_ADC_IO (C15.1), TSW12J64EVM_B_5_FMC (FMC_RX1.A11)
D4_N: TSW12J64EVM_B_4_ADC_IO (C21.1), TSW12J64EVM_B_5_FMC (FMC_RX1.A14)
D4_P: TSW12J64EVM_B_4_ADC_IO (C20.1), TSW12J64EVM_B_5_FMC (FMC_RX1.A15)
D5_N: TSW12J64EVM_B_4_ADC_IO (C23.1), TSW12J64EVM_B_5_FMC (FMC_RX1.A18)
D5_P: TSW12J64EVM_B_4_ADC_IO (C22.1), TSW12J64EVM_B_5_FMC (FMC_RX1.A19)
D6_N: TSW12J64EVM_B_4_ADC_IO (C28.1), TSW12J64EVM_B_5_FMC (FMC_RX1.B16)
D6_P: TSW12J64EVM_B_4_ADC_IO (C26.1), TSW12J64EVM_B_5_FMC (FMC_RX1.B17)
D7_N: TSW12J64EVM_B_4_ADC_IO (C31.1), TSW12J64EVM_B_5_FMC (FMC_RX1.B12)
D7_P: TSW12J64EVM_B_4_ADC_IO (C29.1), TSW12J64EVM_B_5_FMC (FMC_RX1.B13)
FMC_ADC_CLK: TSW12J64EVM_B_5_FMC (FMC_RX1.H37), TSW12J64EVM_B_10_InterfaceControl (R58.2)
FMC_ADC_SCSb0: TSW12J64EVM_B_5_FMC (FMC_RX1.H38), TSW12J64EVM_B_10_InterfaceControl (R54.2)
FMC_ADC_SDI: TSW12J64EVM_B_5_FMC (FMC_RX1.G36), TSW12J64EVM_B_10_InterfaceControl (R57.2)
FMC_ADC_SDO: TSW12J64EVM_B_5_FMC (FMC_RX1.G37), TSW12J64EVM_B_10_InterfaceControl (R55.2)
FMC_DEVCLK_N: TSW12J64EVM_B_4_ADC_IO (C93.2), TSW12J64EVM_B_5_FMC (FMC_RX1.K29)
FMC_DEVCLK_P: TSW12J64EVM_B_4_ADC_IO (C92.2), TSW12J64EVM_B_5_FMC (FMC_RX1.K28)
FMC_SCL: TSW12J64EVM_B_5_FMC (FMC_RX1.C30 J1.2 U16.6), TSW12J64EVM_B_10_InterfaceControl (R127.2)
FMC_SDA: TSW12J64EVM_B_5_FMC (FMC_RX1.C31 J1.1 U16.5), TSW12J64EVM_B_10_InterfaceControl (R126.2)
FMC_SPI_CLK: TSW12J64EVM_B_5_FMC (FMC_RX1.G30), TSW12J64EVM_B_10_InterfaceControl (R121.2)
FMC_SPI_SCSb1: TSW12J64EVM_B_5_FMC (FMC_RX1.G33), TSW12J64EVM_B_10_InterfaceControl (R69.2)
FMC_SPI_SCSb2: TSW12J64EVM_B_5_FMC (FMC_RX1.G34), TSW12J64EVM_B_10_InterfaceControl (R119.2)
FMC_SPI_SDIO: TSW12J64EVM_B_5_FMC (FMC_RX1.H34), TSW12J64EVM_B_10_InterfaceControl (R120.2)
FMC_SYSREF_N: TSW12J64EVM_B_4_ADC_IO (C91.2), TSW12J64EVM_B_5_FMC (FMC_RX1.K38)
FMC_SYSREF_P: TSW12J64EVM_B_4_ADC_IO (C90.2), TSW12J64EVM_B_5_FMC (FMC_RX1.K37)
FTDI_TRF_R1: TSW12J64EVM_B_6_TRF3765 (U4.6), TSW12J64EVM_B_10_InterfaceControl (U13.43)
IN_N: TSW12J64EVM_B_1_FRONT_END (K5.2), TSW12J64EVM_B_3_ANALOG_IN (C295.2 R203.1)
IN_P: TSW12J64EVM_B_1_FRONT_END (K5.7), TSW12J64EVM_B_3_ANALOG_IN (C296.2 R169.2)
K1_Ax: TSW12J64EVM_B_1_FRONT_END (K1.5 K1_Ax.1), TSW12J64EVM_B_2_RELAY_CONTROL (U27.16)
K1_Bx: TSW12J64EVM_B_1_FRONT_END (K1.10 K1_Bx.1), TSW12J64EVM_B_2_RELAY_CONTROL (U27.15)
K2_Ax: TSW12J64EVM_B_1_FRONT_END (K2.5 K2_Ax.1), TSW12J64EVM_B_2_RELAY_CONTROL (U27.14)
K2_Bx: TSW12J64EVM_B_1_FRONT_END (K2.10 K2_Bx.1), TSW12J64EVM_B_2_RELAY_CONTROL (U27.13)
K3_Ax: TSW12J64EVM_B_1_FRONT_END (K3.5 K3_Ax.1), TSW12J64EVM_B_2_RELAY_CONTROL (U27.12)
K3_Bx: TSW12J64EVM_B_1_FRONT_END (K3.10 K3_Bx.1), TSW12J64EVM_B_2_RELAY_CONTROL (U29.16)
K4_Ax: TSW12J64EVM_B_1_FRONT_END (K4.5 K4_Ax.1), TSW12J64EVM_B_2_RELAY_CONTROL (U29.15)
K4_Bx: TSW12J64EVM_B_1_FRONT_END (K4.10 K4_Bx.1), TSW12J64EVM_B_2_RELAY_CONTROL (U29.14)
K5_Ax: TSW12J64EVM_B_1_FRONT_END (K5.5 K5_Ax.1), TSW12J64EVM_B_2_RELAY_CONTROL (U29.13)
K5_Bx: TSW12J64EVM_B_1_FRONT_END (K5.10 K5_Bx.1), TSW12J64EVM_B_2_RELAY_CONTROL (U29.12)
LM95233_SMBCLK: TSW12J64EVM_B_4_ADC_IO (R32.1 U3.13), TSW12J64EVM_B_10_InterfaceControl (R125.1 R127.1)
LM95233_SMBDAT: TSW12J64EVM_B_4_ADC_IO (R31.1 U3.12), TSW12J64EVM_B_10_InterfaceControl (R117.1 R124.1 R126.1)
LMH_SCLK: TSW12J64EVM_B_3_ANALOG_IN (U23.14), TSW12J64EVM_B_10_InterfaceControl (U24.14)
LMH_SCSb: TSW12J64EVM_B_3_ANALOG_IN (U23.15), TSW12J64EVM_B_10_InterfaceControl (R187.1 U24.11)
LMH_SDI: TSW12J64EVM_B_3_ANALOG_IN (U23.1), TSW12J64EVM_B_10_InterfaceControl (U24.13)
LMH_SDO: TSW12J64EVM_B_3_ANALOG_IN (U23.4), TSW12J64EVM_B_10_InterfaceControl (U24.12)
LMK_TRF_CLK: TSW12J64EVM_B_6_TRF3765 (U4.4), TSW12J64EVM_B_10_InterfaceControl (R102.1 R115.1 R121.1 R129.2)
LMK_TRF_DATA: TSW12J64EVM_B_6_TRF3765 (U4.3), TSW12J64EVM_B_10_InterfaceControl (R101.1 R114.1 R120.1 R128.2)
NCO_0: TSW12J64EVM_B_4_ADC_IO (R136.2), TSW12J64EVM_B_5_FMC (FMC_RX1.E12)
NCO_1: TSW12J64EVM_B_4_ADC_IO (R137.2), TSW12J64EVM_B_5_FMC (FMC_RX1.E13)
NCO_2: TSW12J64EVM_B_4_ADC_IO (R138.2), TSW12J64EVM_B_5_FMC (FMC_RX1.E36)
SYNC_N: TSW12J64EVM_B_4_ADC_IO (R20.2), TSW12J64EVM_B_5_FMC (FMC_RX1.G13)
SYNC_P: TSW12J64EVM_B_4_ADC_IO (R19.2), TSW12J64EVM_B_5_FMC (FMC_RX1.G12)
SYNC_SE: TSW12J64EVM_B_4_ADC_IO (R134.1), TSW12J64EVM_B_5_FMC (FMC_RX1.H31)
TRF3765_STROBE: TSW12J64EVM_B_6_TRF3765 (U4.5), TSW12J64EVM_B_10_InterfaceControl (R97.1 R113.1 R116.2 R119.1)
TRF_OutB_N: TSW12J64EVM_B_4_ADC_IO (C33.2), TSW12J64EVM_B_6_TRF3765 (C83.2 R36.2)
TRF_OutB_P: TSW12J64EVM_B_4_ADC_IO (C32.2), TSW12J64EVM_B_6_TRF3765 (C75.2 R29.2)
Vcmo: TSW12J64EVM_B_3_ANALOG_IN (C310.2 R239.2 U25.1), TSW12J64EVM_B_4_ADC_IO (Vcmo.2)
VIN_N: TSW12J64EVM_B_3_ANALOG_IN (R180.2), TSW12J64EVM_B_4_ADC_IO (U2.9)
VIN_P: TSW12J64EVM_B_3_ANALOG_IN (R179.2), TSW12J64EVM_B_4_ADC_IO (U2.8)

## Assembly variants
001: not fitted C30 C36 C85 C86 C87 C90 C91 C92 C93 C114 C123 C230 C231 C234 C235 C247 C250 C251 C262 C263 C370 C371 C372 C373 C374 C375 C376 C377 C378 C379 C380 C381 F1 FID1 FID2 FID3 R7 R8 R9 R18 R21 R22 R23 R24 R26 R29 R30 R36 R40 R42 R50 R54 R55 R57 R58 R69 R73 R75 R83 R84 R90 R92 R95 R104 R116 R119 R120 R121 R126 R127 R128 R129 R139 R140 R141 R142 R146 R151 R153 R165 R178 R239 R240 R241 U16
